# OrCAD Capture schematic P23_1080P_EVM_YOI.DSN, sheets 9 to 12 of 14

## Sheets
9 P08: Frame Buffer Memory: size D
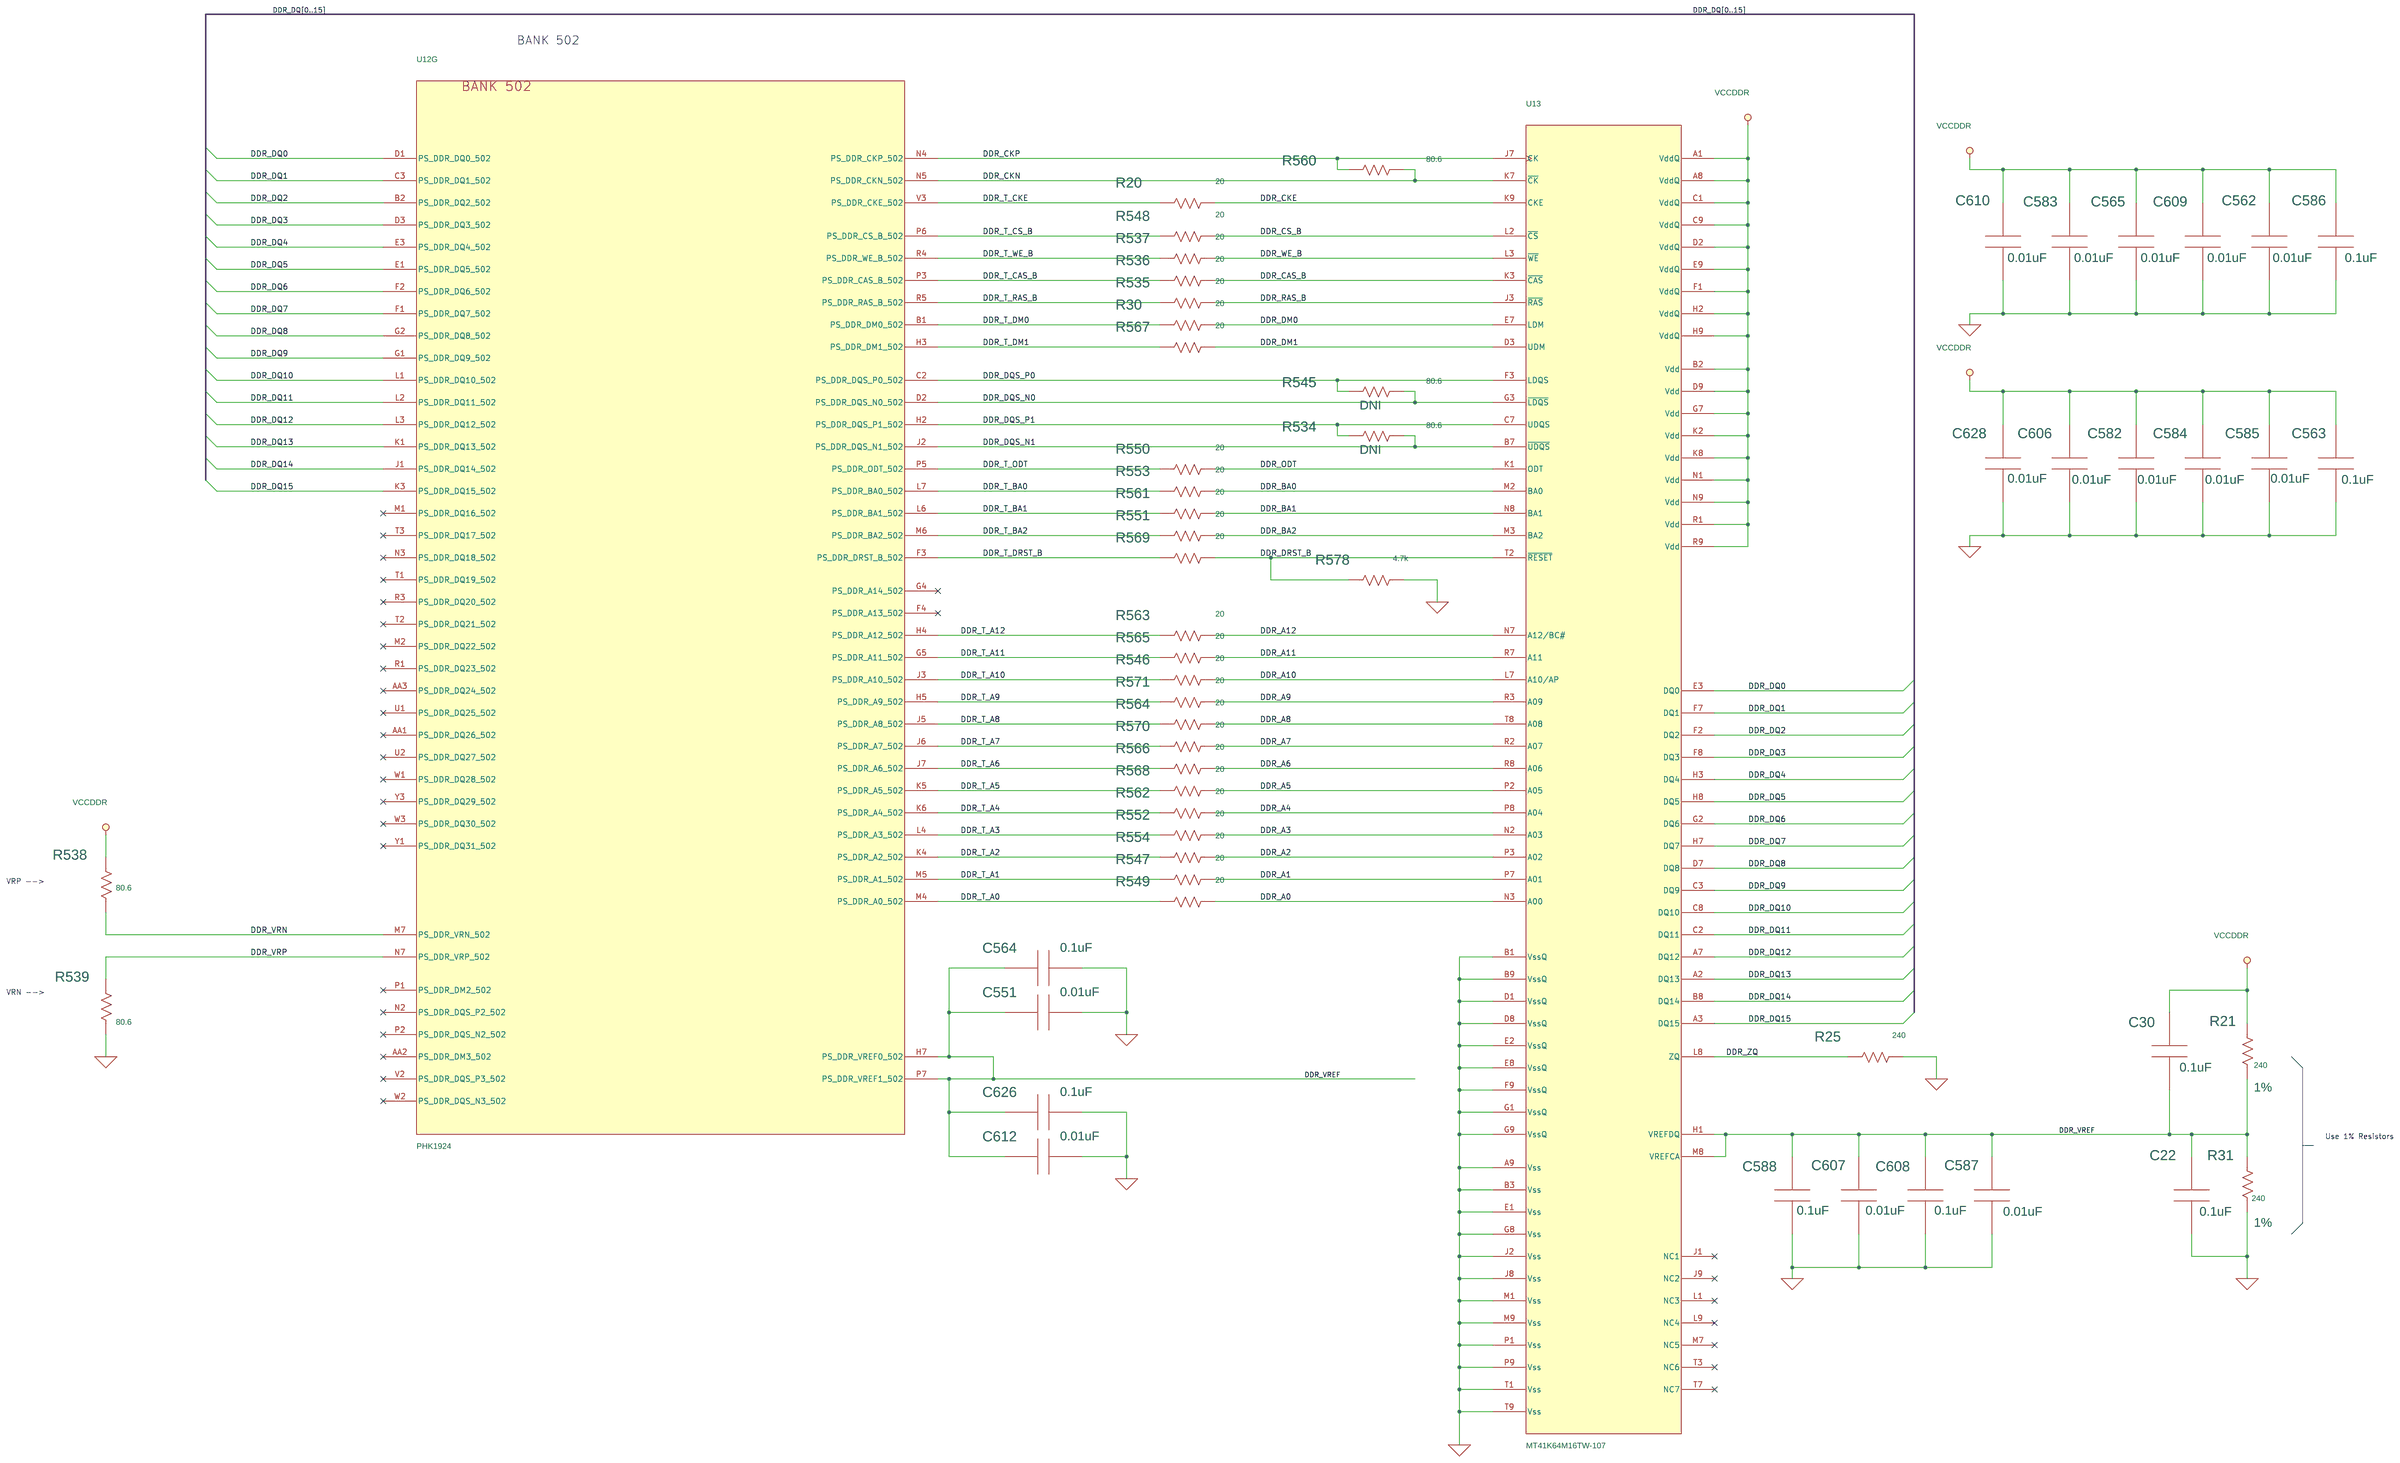
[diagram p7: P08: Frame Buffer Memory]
10 P09: FPGA Parallal Video IN: size D
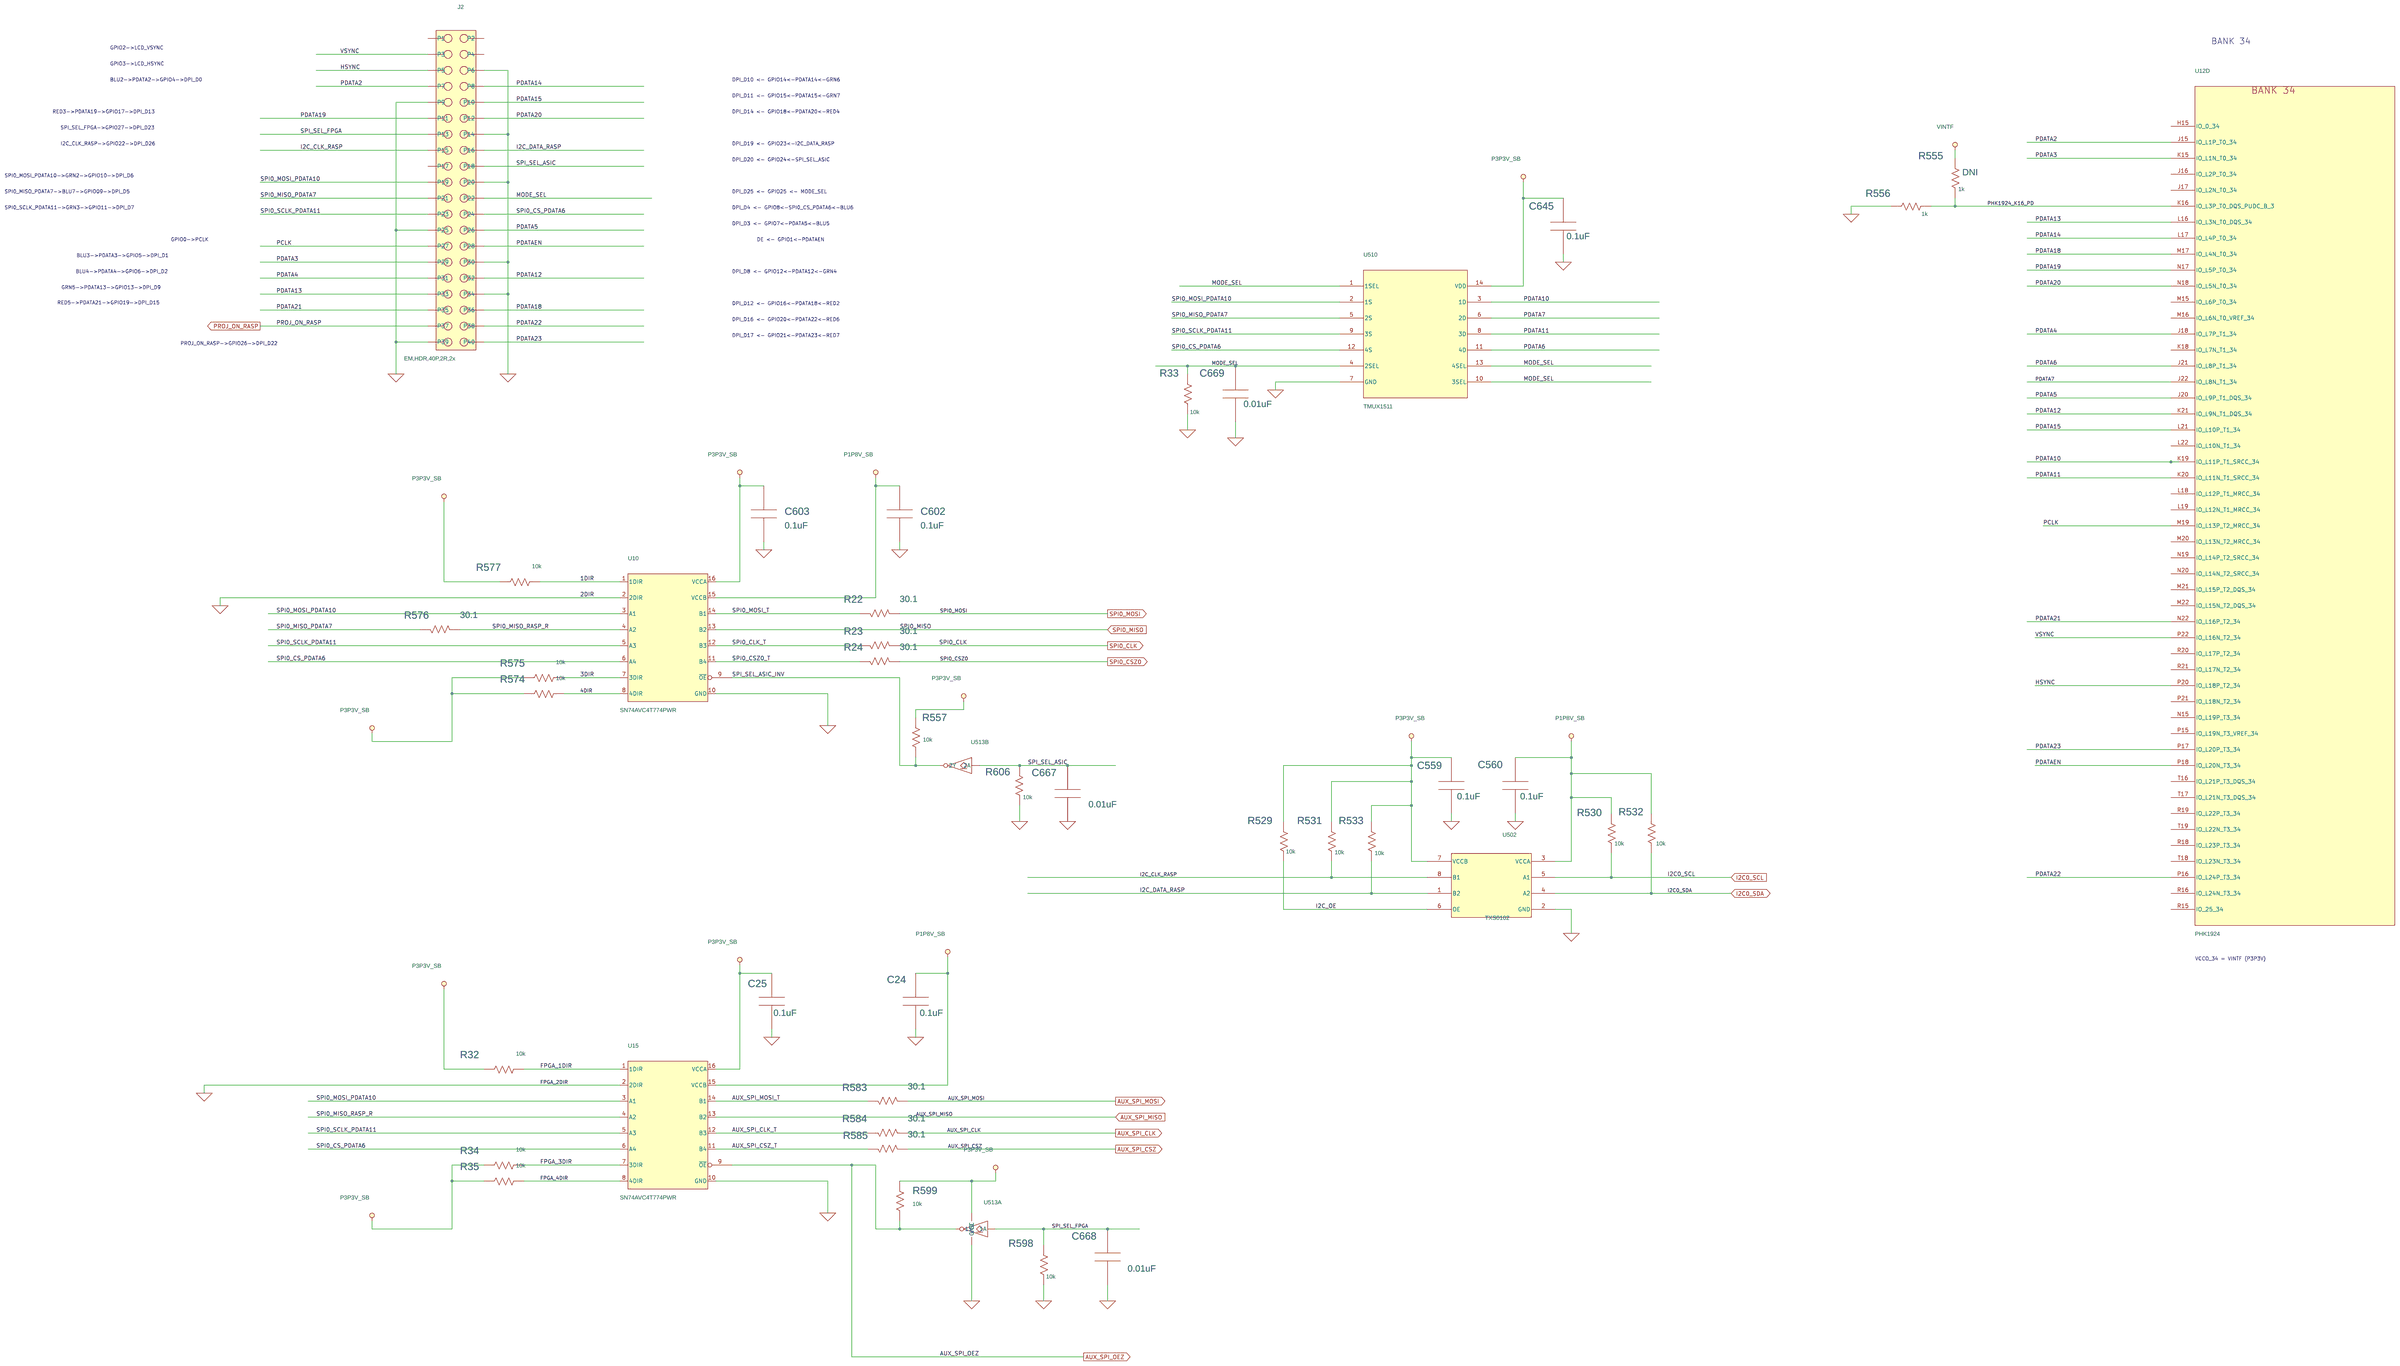
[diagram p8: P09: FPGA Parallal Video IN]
11 P02: BOOT, FLSH, RST,DEBUG: size D
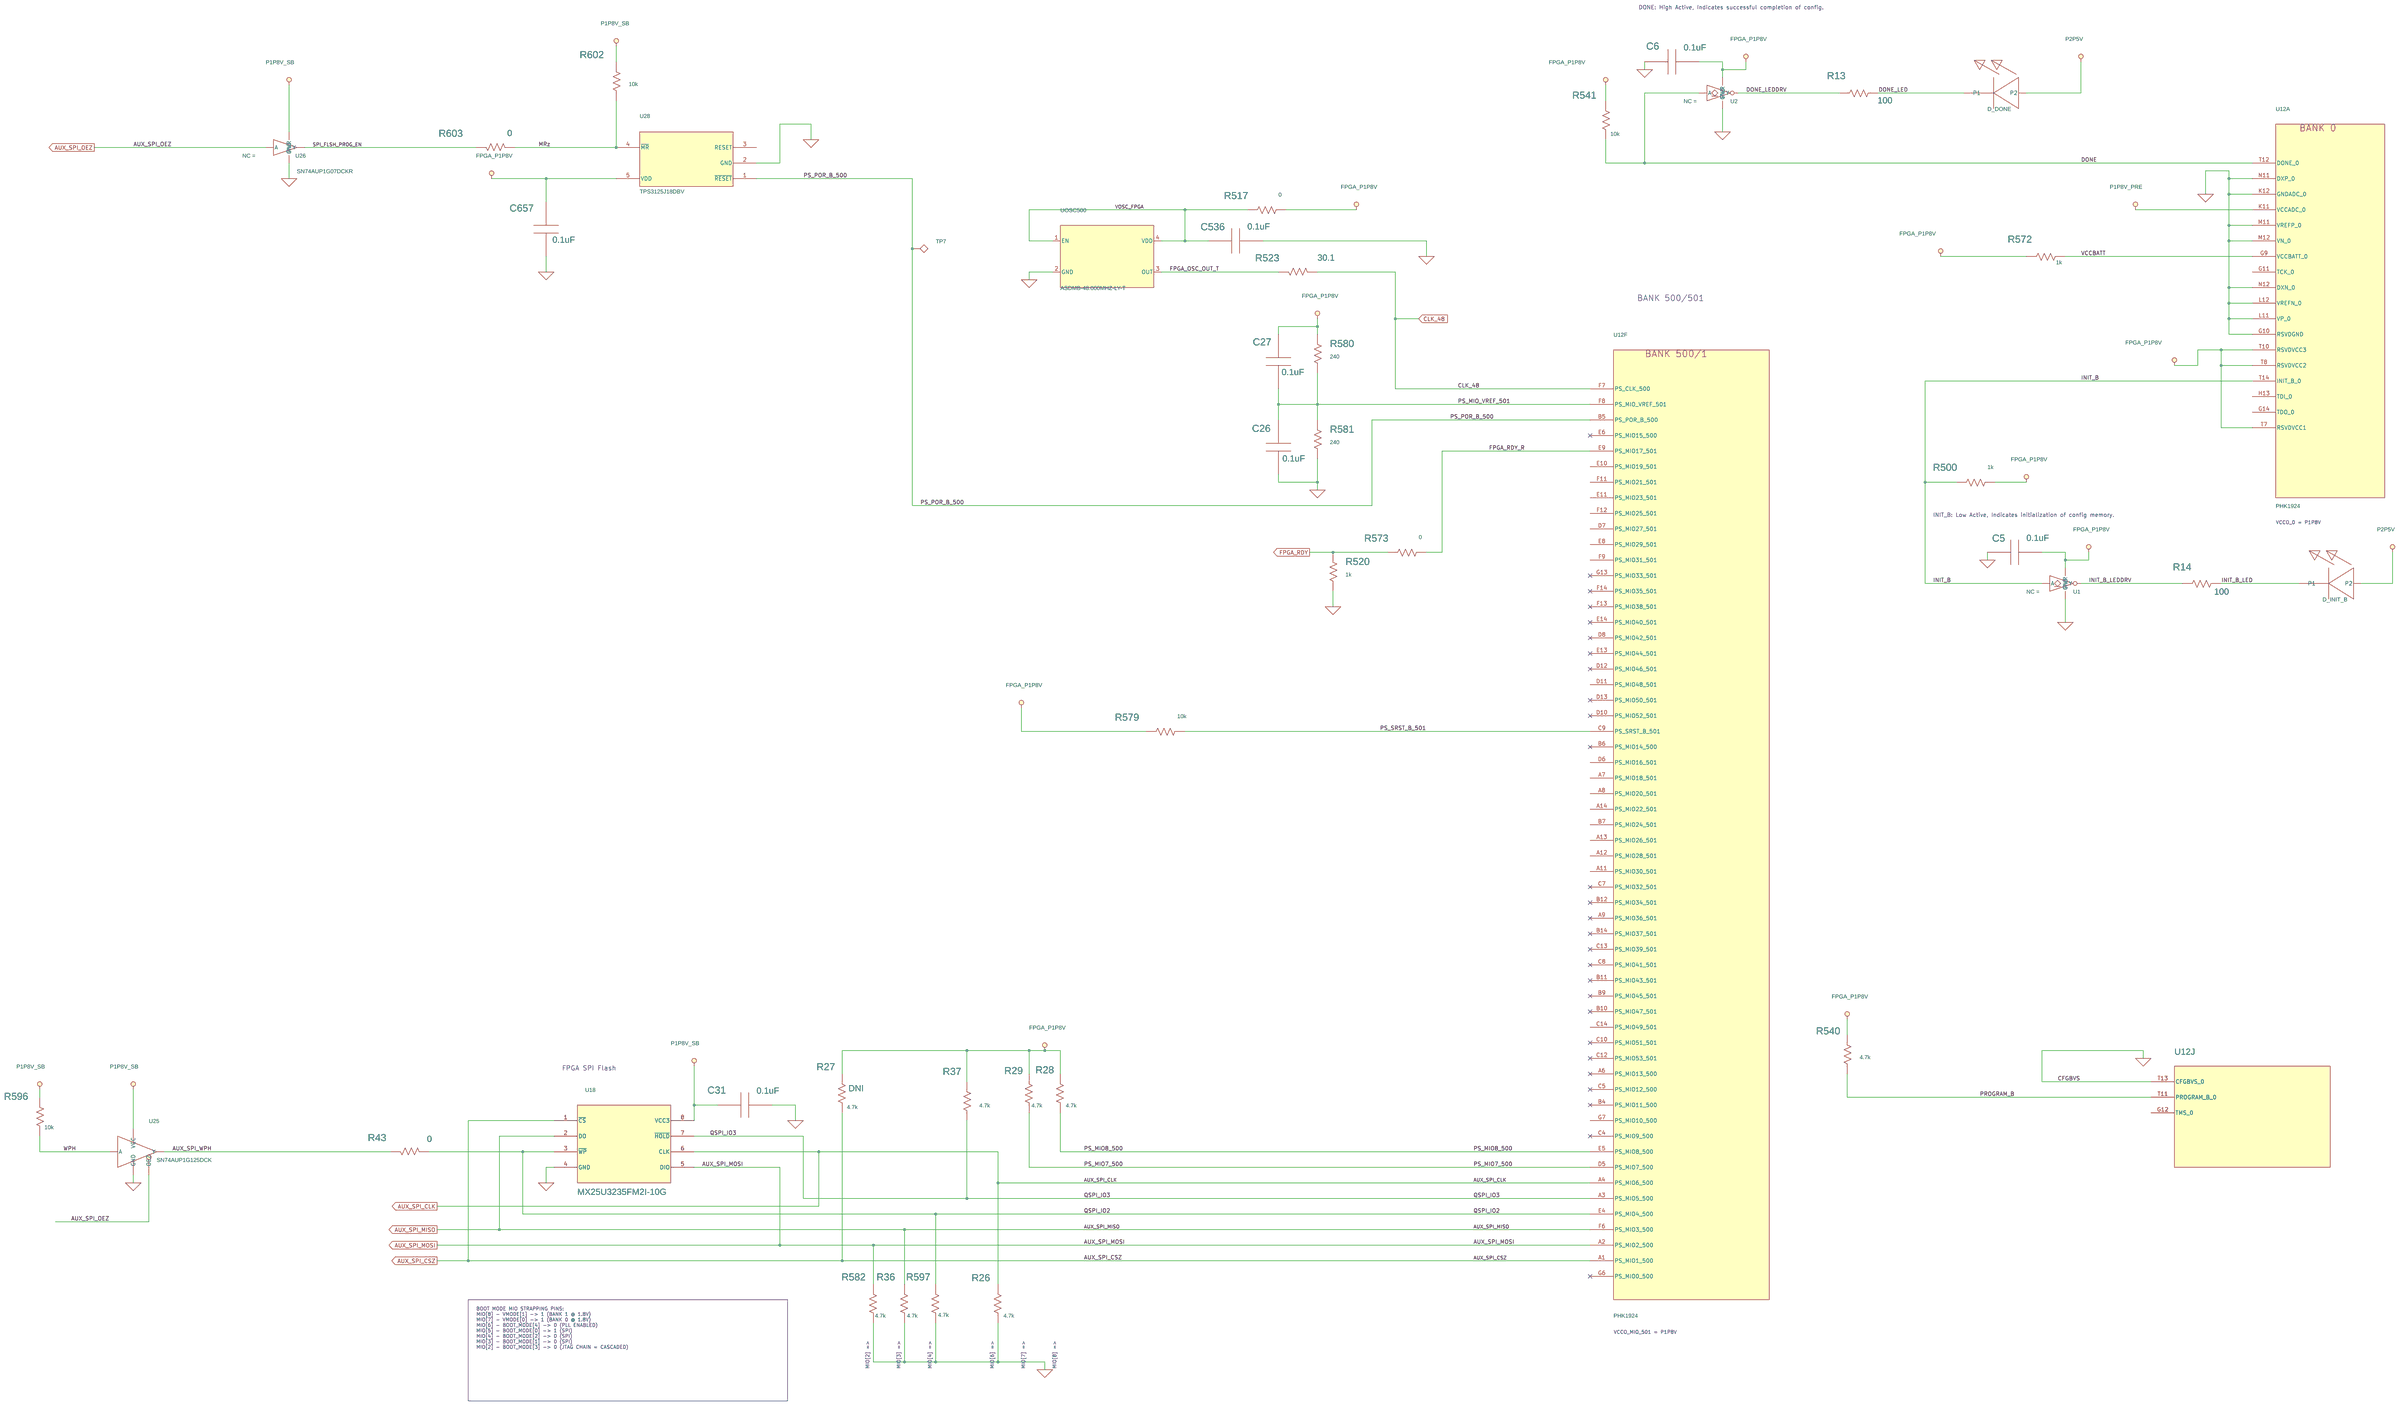
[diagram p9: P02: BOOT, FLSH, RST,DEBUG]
12 P06: DLPC3436 Parallel Video IN: size D
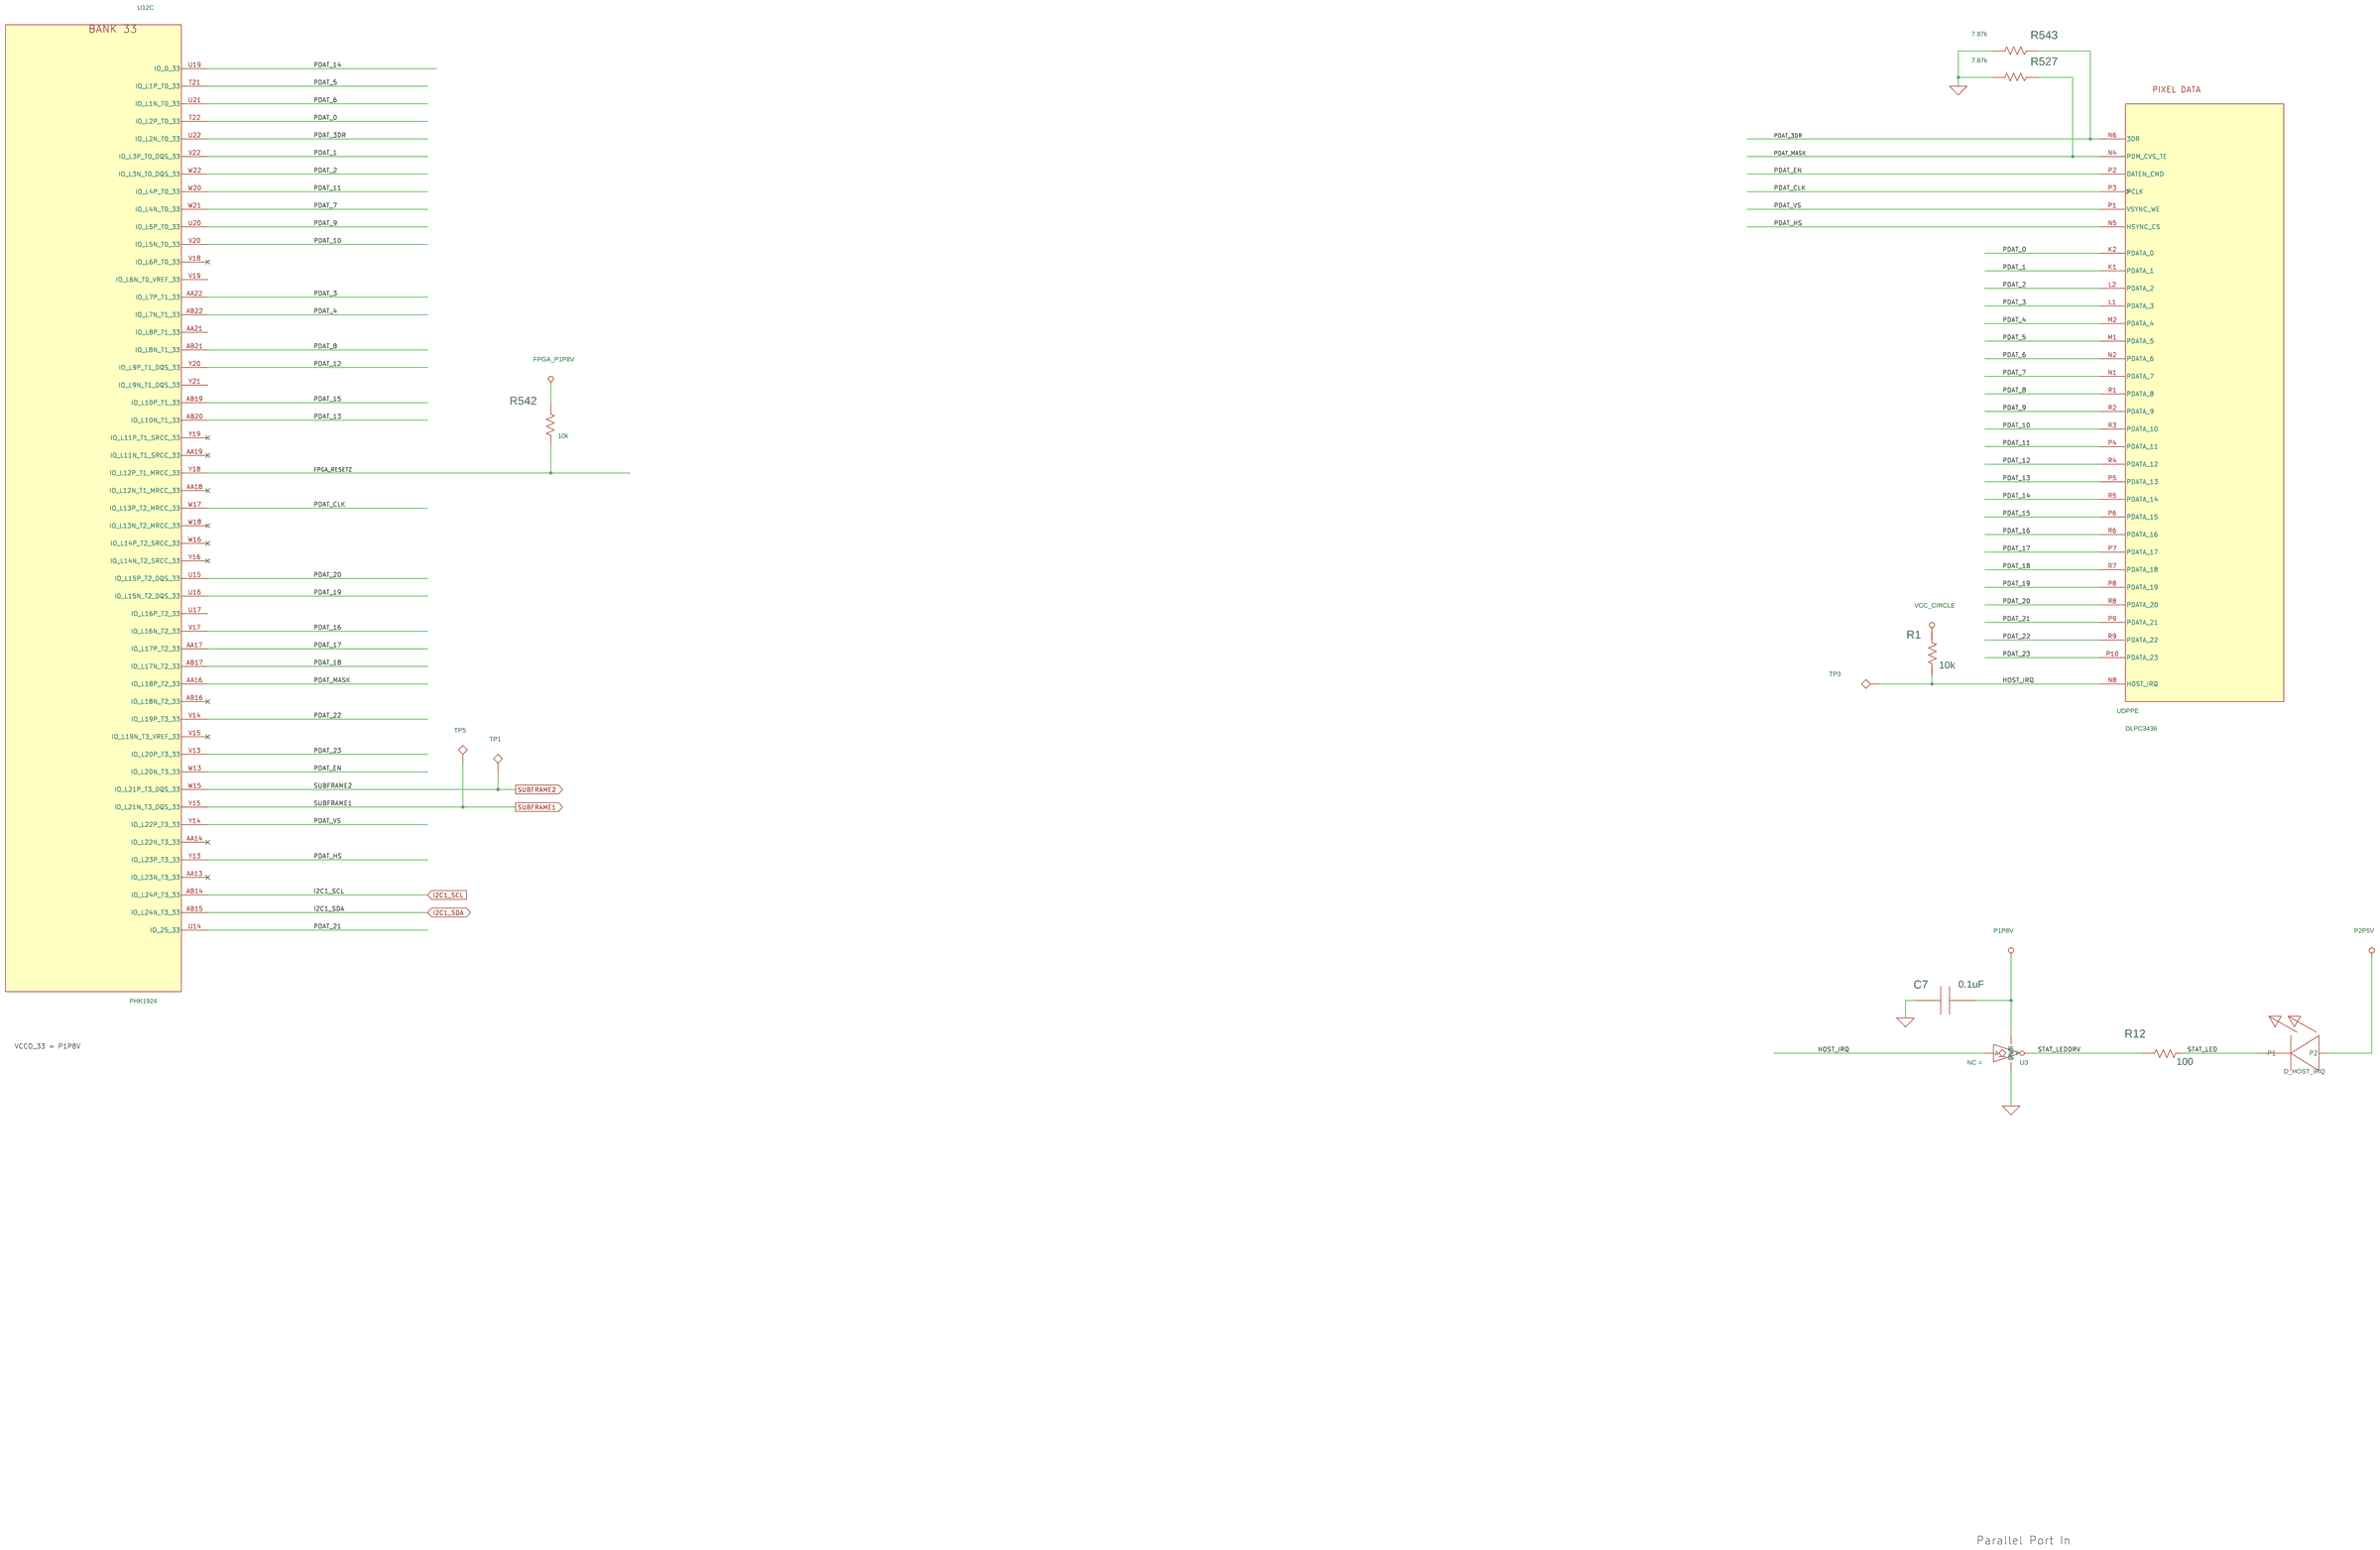
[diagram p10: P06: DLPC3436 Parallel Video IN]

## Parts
sheet P02: BOOT, FLSH, RST,DEBUG
C5  0.1uF  [0402_AVXA]
C6  0.1uF  [0402_AVXA]
C26  0.1uF  [0402_AVXA]
C27  0.1uF  [0402_AVXA]
C31  0.1uF  [0402_AVXA]
C536  0.1uF  [0402_AVXA]
C657  0.1uF  [0402_AVXA]
D_DONE  green  [1206]
D_INIT_B  green  [1206]
R13  100  [0402]
R14  100  [0402]
R26  4.7k  [0402]
R27  4.7k  [0402]
R28  4.7k  [0402]
R29  4.7k  [0402]
R36  4.7k  [0402]
R37  4.7k  [0402]
R43  0  [0402]
R500  1k  [0402]
R517  0  [0402]
R520  1k  [0402]
R523  30.1  [0402]
R540  4.7k  [0402]
R541  10k  [0402]
R572  1k  [0402]
R573  0  [0402]
R579  10k  [0402]
R580  240  [0402]
R581  240  [0402]
R582  4.7k  [0402]
R596  10k  [0402]
R597  4.7k  [0402]
R602  10k  [0402]
R603  0  [0402]
TP7  TP40  [TP40]
U1  SN74AUP1G06DCK  [U_5_DCK]
U2  SN74AUP1G06DCK  [U_5_DCK]
U18  MX25U3235FM2I-10G  [SOIC-8_208mil]
U25  SN74AUP1G125DCK  [U_5_DCK]
U26  SN74AUP1G07DCK  [U_5_DCK]
U28  TPS3125J18DBV  [DBV_R-PDS0-G5]
UOSC500  48MHz  [ECS-2018_2p5mmx2mm]
sheet P06: DLPC3436 Parallel Video IN
C7  0.1uF  [0402_AVXA]
D_HOST_IRQ  green  [1206]
R1  10k  [0402]
R12  100  [0402]
R527  7.87k  [0402]
R542  10k  [0402]
R543  7.87k  [0402]
TP1  TP,20mil PAD  [tp20rd]
TP3  TP40  [TP40]
TP5  TP40  [TP40]
U3  SN74AUP1G06DCK  [U_5_DCK]
sheet P08: Frame Buffer Memory
C22  0.1uF  [0402_AVXA]
C30  0.1uF  [0402_AVXA]
C551  0.01uF  [0402]
C562  0.01uF  [0402]
C563  0.1uF  [0402_AVXA]
C564  0.1uF  [0402_AVXA]
C565  0.01uF  [0402]
C582  0.01uF  [0402]
C583  0.01uF  [0402]
C584  0.01uF  [0402]
C585  0.01uF  [0402]
C586  0.1uF  [0402_AVXA]
C587  0.01uF  [0402]
C588  0.1uF  [0402_AVXA]
C606  0.01uF  [0402]
C607  0.01uF  [0402]
C608  0.1uF  [0402_AVXA]
C609  0.01uF  [0402]
C610  0.01uF  [0402]
C612  0.01uF  [0402]
C626  0.1uF  [0402_AVXA]
C628  0.01uF  [0402]
R20  20  [0201_R]
R21  240  [0402]
R25  240  [0402]
R30  20  [0201_R]
R31  240  [0402]
R534  80.6  [0402]
R535  20  [0201_R]
R536  20  [0201_R]
R537  20  [0201_R]
R538  80.6  [0402]
R539  80.6  [0402]
R545  80.6  [0402]
R546  20  [0201_R]
R547  20  [0201_R]
R548  20  [0201_R]
R549  20  [0201_R]
R550  20  [0201_R]
R551  20  [0201_R]
R552  20  [0201_R]
R553  20  [0201_R]
R554  20  [0201_R]
R560  80.6  [0402]
R561  20  [0201_R]
R562  20  [0201_R]
R563  20  [0201_R]
R564  20  [0201_R]
R565  20  [0201_R]
R566  20  [0201_R]
R567  20  [0201_R]
R568  20  [0201_R]
R569  20  [0201_R]
R570  20  [0201_R]
R571  20  [0201_R]
R578  4.7k  [0402]
U12  PHK1924  [Xilinx_CLG484]  (sections A,B,C,D,E,F,G,H,I,J)
U13  MT41K64M16TW-107  [Micron_96-ball_FBGA-x16_TW]
sheet P09: FPGA Parallal Video IN
C24  0.1uF  [0402_AVXA]
C25  0.1uF  [0402_AVXA]
C559  0.1uF  [0402_AVXA]
C560  0.1uF  [0402_AVXA]
C602  0.1uF  [0402_AVXA]
C603  0.1uF  [0402_AVXA]
C645  0.1uF  [0402_AVXA]
C667  0.01uF  [0402]
C668  0.01uF  [0402]
C669  0.01uF  [0402]
J2  EM,HDR,40P,2R,2x  [MINI_HDR20X2]
R22  30.1  [0402]
R23  30.1  [0402]
R24  30.1  [0402]
R32  10k  [0402]
R33  10k  [0402]
R34  10k  [0402]
R35  10k  [0402]
R529  10k  [0402]
R530  10k  [0402]
R531  10k  [0402]
R532  10k  [0402]
R533  10k  [0402]
R555  1k  [0402]
R556  1k  [0402]
R557  10k  [0402]
R574  10k  [0402]
R575  10k  [0402]
R576  30.1  [0402]
R577  10k  [0402]
R583  30.1  [0402]
R584  30.1  [0402]
R585  30.1  [0402]
R598  10k  [0402]
R599  10k  [0402]
R606  10k  [0402]
U10  SN74AVC4T774PWR  [TSSOP16_PW]
U15  SN74AVC4T774PWR  [TSSOP16_PW]
U502  TXS0102  [VSSOP-8_DCU]
U510  TMUX1511  [TSSOP14_PW]
U513  SN74AUP2G06DCKR  [U_6_DCK]  (sections A,B)
sheet P10: DLPA2005
UDPP  DLPC3436  [DPP3433_7mmx7mm_VFBGA_176balls]  (sections A,B,C,D,E,F,G,H)

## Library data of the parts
C5-C7 C22 C24-C27 C30 C31 C536 C559 C560 C563 C564 C586 C588 C602 C603 C608 C626 C645 = PAS,CAP,NP,large: DigiKey: 490-7998-1-ND; DigiReel: 490-7998-6-ND; Family: passive; Lead Style: SMT; MFG: Murata; Material: x7r; P/D_NUM: GCM155R71C104KA55J; Part Number: GCM155R71C104KA55J; Part Specific: CAP CER .1UF 16V X7R 0402; TOLERANCE: 10%; Type: capacitor; VENDOR: Murata; VPC: 16V
C657 = PAS,CAP,NP,large: DigiKey: 490-7998-1-ND; DigiReel: 490-7998-6-ND; Family: passive; Install: Y; Lead Style: SMT; MFG: Murata; Material: x7r; P/D_NUM: GCM155R71C104KA55J; Part Number: GCM155R71C104KA55J; Part Specific: CAP CER .1UF 16V X7R 0402; TOLERANCE: 10%; Type: capacitor; VENDOR: Murata; VPC: 16V
D_DONE D_HOST_IRQ D_INIT_B = PAS,DIODE,LED,large: DigiKey: 67-1357-1-ND; DigiReel: 67-1357-6-ND; Family: passive; Index PN: 31; Install: Y; Lead Style: SMT; MFG: Lumex; P/D_NUM: SML-LX1206GC-TR; Part Number: SML-LX1206GC-TR; Part Specific: LED 565NM WTR CLR GREEN 1206 SMD; Type: diode,led; VENDOR: Lumex
R12-R14 = PAS,R,large: DigiKey: P100LCT-ND; DigiReel: P100LDKR-ND; Family: passive; Index PN: 690; Lead Style: SMT; MFG: Panasonic; Material: chip; P/D_NUM: ERJ-2RKF1000X; Part Number: ERJ-2RKF1000X; Part Specific: RES 100 OHM 1/10W 1% 0402 SMD; Power: 1/16W; TOLERANCE: 1%; Type: resistor; VENDOR: Panasonic; VPC: 1/16W
R26 R28 R29 R36 R37 R540 R578 R597 = PAS,R,large: DigiKey: P4.70KLCT-ND; DigiReel: P4.70KLDKR-ND; Family: passive; Index PN: 1219; Lead Style: SMT; MFG: Panasonic; P/D_NUM: ERJ-2RKF4701X; Part Number: ERJ-2RKF4701X; Part Specific: RES 4.7K OHM 1/10W 1% 0402 SMD; Type: resistor; VENDOR: Panasonic; VPC: 1/16W
R27 = PAS,R,large: DigiKey: P4.70KLCT-ND; DigiReel: P4.70KLDKR-ND; Family: passive; Index PN: 1219; Install: DNI; Lead Style: SMT; MFG: Panasonic; P/D_NUM: ERJ-2RKF4701X; Part Number: ERJ-2RKF4701X; Part Specific: RES 4.7K OHM 1/10W 1% 0402 SMD; Type: resistor; VENDOR: Panasonic; VPC: 1/16W
R43 R603 = PAS,R,large: DigiKey: P0.0JCT-ND; DigiReel: P0.0JDKR-ND; Family: passive; Index PN: 687; Install: Y; Lead Style: SMT; MFG: Panasonic; Material: chip; P/D_NUM: ERJ-2GE0R00X; Part Number: ERJ-2GE0R00X; Part Specific: RES 0.0 OHM 1/16W 0402 SMD; Power: 1/16W; Type: resistor; VPC: 1/16W; Vendor: Panasonic
R500 R520 R556 R572 = PAS,R,large: DigiKey: P1.00KLCT-ND; DigiReel: P1.00KLDKR-ND; Family: passive; Index PN: 684; Install: Y; Lead Style: SMT; MFG: Panasonic; Material: chip; P/D_NUM: ERJ-2RKF1001X; Part Number: ERJ-2RKF1001X; Part Specific: RES 1.00K OHM 1/10W 1% 0402 SMD; Power: 1/16W; TOLERANCE: 1%; Type: resistor; VENDOR: Panasonic; VPC: 1/16W
R517 R573 = PAS,R,large: DigiKey: P0.0JCT-ND; DigiReel: P0.0JDKR-ND; Family: passive; Index PN: 687; Lead Style: SMT; MFG: Panasonic; Material: chip; P/D_NUM: ERJ-2GE0R00X; Part Number: ERJ-2GE0R00X; Part Specific: RES 0.0 OHM 1/16W 0402 SMD; Power: 1/16W; Type: resistor; VENDOR: Panasonic; VPC: 1/16W
R22-R24 R523 R576 R583-R585 = PAS,R,large: DigiKey: YAG3111CT-ND; DigiReel: P30.1LDKR-ND; Family: passive; Index PN: 976; Lead Style: SMT; MFG: Yageo; Material: chip; P/D_NUM: RC0402FR-0730R1L; Part Number: RC0402FR-0730R1L; Part Specific: RES 30.1 OHM 1/16W 1% 0402 SMD; Power: 1/16W; TOLERANCE: 1%; Type: resistor; VENDOR: Yageo; VPC: 1/16W
R541 R542 R579 R596 R602 = PAS,R,large: DigiKey: P10.0KLCT-ND; DigiReel: P10.0KLDKR-ND; Family: passive; Index PN: 680; Install: Y; Lead Style: SMT; MFG: Panasonic; Material: chip; P/D_NUM: ERJ-2RKF1002X; Part Number: ERJ-2RKF1002X; Part Specific: RES SMD 10K OHM 1% 1/10W 0402; Power: 1/16W; TOLERANCE: 1%; Type: resistor; VENDOR: Panasonic; VPC: 1/16W
R21 R25 R31 R580 R581 = PAS,R,large: DigiKey: P240LCT-ND; DigiReel: P240LDKR-ND; Family: passive; Index PN: 1303; Lead Style: SMT; MFG: Panasonic; P/D_NUM: ERJ-2RKF2400X; Part Number: ERJ-2RKF2400X; Part Specific: RES SMD 240 OHM 1% 1/10W 0402; TOLERANCE: 1%; Type: resistor; VENDOR: Panasonic; VPC: 1/16W
R582 = PAS,R,large: DigiKey: P4.70KLCT-ND; DigiReel: P4.70KLDKR-ND; Family: passive; Index PN: 1219; Install: Y; Lead Style: SMT; MFG: Panasonic; P/D_NUM: ERJ-2RKF4701X; Part Number: ERJ-2RKF4701X; Part Specific: RES 4.7K OHM 1/10W 1% 0402 SMD; Type: resistor; VENDOR: Panasonic; VPC: 1/16W
TP3 TP5 TP7 = EM,TERM,TESTPOINT: DigiKey: ---; DigiReel: ---; Family: board feature; Index PN: 995; Install: DNI; MFG: -- NOT A PART --; Type: hole,plated; Vendor: -- NOT A PART --
U1-U3 = LOG,INV,OPENDRN,SN74AUP1G06DCK: DigiKey: 296-17562-1-ND; DigiReel: 296-17562-6-ND; Family: logic; Index PN: 1026; Lead Style: SMT; MFG: Texas Instruments; P/D_NUM: SN74AUP1G06DCKR; Part Number: SN74AUP1G06DCKR; Part Specific: IC INVERTER SINGLE 1INPUT SC705, open drain; Type: buffer
U18 = MEM,FLASH,SERIAL,W25XxxALxNIG: DigiKey: 1092-1137-ND; DigiReel: ---; Family: memory; Install: Y; Lead Style: SMT; MFG: Macronix; Part Specific: IC FLASH 32MBIT 104MHZ 8SOIC; Type: flash, spi; VENDOR: Macronix; VPC: 1.65-1.95V
U25 = LOG,BUF,SN74AUP1G125DCK: DigiKey: 296-21012-1-ND; DigiReel: 296-21012-6-ND; Family: logic; Lead Style: SMT; MFG: Texas Instruments; P/D_NUM: SN74AUP1G125DCKR; Part Number: SN74AUP1G125DCKR; Part Specific: IC BUS BUFFER TRI-ST SC70-5; Pin Cnt: 5; Type: buffer
U26 = LOG,BUF,OPENDRN,SN74AUP1G07DCK: DigiKey: 296-18256-1-ND; DigiReel: 296-18256-6-ND; Family: logic; Index PN: 1027; Lead Style: SMT; MFG: Texas Instruments; P/D_NUM: SN74AUP1G07DCKR; Part Number: SN74AUP1G07DCKR; Part Specific: IC BUFF/DVR LOW PWR N-INV SC705, open drain; Type: buffer
U28 = PWR,MON,TPS3125: DigiKey: 296-10898-1-ND; DigiReel: 296-10898-6-ND; Family: power; Index PN: 1160; Install: Y; Lead Style: SMT; MFG: Texas Instruments; Part Specific: IC 1.62V SUPPLY MONITOR SOT23-5; Type: monitor; Vendor: Texas Instruments
UOSC500 = ANA,OSC,4P,2X: DigiKey: 535-11198-1-ND; DigiReel: 535-11198-6-ND; Family: analog; Index PN: 1346; Install: Y; Lead Style: SMT; MFG: Abracon; P/D_NUM: ASDMB-48.000MHZ-LY-T; Part Number: ASDMB-48.000MHZ-LY-T; Part Specific: OSC MEMS 48.000MHZ CMOS SMD; Type: oscillator; VPC: 1.8V-3.3V; Vendor: Abracon
R1 R529 = PAS,R,large: DigiKey: P10.0KLCT-ND; DigiReel: P10.0KLDKR-ND; Family: passive; Index PN: 680; Install: Y; Lead Style: SMT; MFG: Panasonic; Material: chip; P/D_NUM: ERJ-2RKF1002X; Part Number: ERJ-2RKF1002X; Part Specific: RES SMD 10K OHM 1% 1/10W 0402; Power: 1/16W; TOLERANCE: 1%; Type: resistor; VPC: 1/16W; Vendor: Panasonic
R527 R543 = PAS,R,large: DigiKey: P7.87KLCT-ND; DigiReel: P7.87KLDKR-ND; Family: passive; Index PN: 1175; Lead Style: SMT; MFG: Panasonic; Material: chip; P/D_NUM: ERJ-2RKF7871X; Part Number: ERJ-2RKF7871X; Part Specific: RES 7.87K OHM 1/10W 1% 0402 SMD; Type: resistor; VENDOR: Panasonic; VPC: 1/10W
TP1 = BF,HOLE,PLATED,TESTPIN: Family: board feature; Index PN: 1145; Install: DNI; Lead Style: SMT; MFG: -- NOT A PART --; Type: pad pattern; Vendor: -- NOT A PART --
C551 C562 C565 C582-C585 C587 C606 C607 C609 C610 C612 C628 = PAS,CAP,NP,large: DigiKey: 399-1038-1-ND; DigiReel: 399-1038-6-ND; Family: passive; Lead Style: SMT; MFG: KEMET; Material: x7r; P/D_NUM: C0402C103K4RACTU; Part Number: C0402C103K4RACTU; Part Specific: CAP CER 10000PF 16V X7R 0402; TOLERANCE: 10%; Type: capacitor; VENDOR: KEMET; VPC: 16V
R20 R30 R535-R537 R546-R554 R561-R571 = PAS,R,large: DigiKey: P20.0ABCT-ND; DigiReel: P20.0ABDKR-ND; Family: passive; Index PN: 1361; Install: Y; Lead Style: SMT; MFG: Panasonic; P/D_NUM: ERJ-1GEF20R0C; Part Number: ERJ-1GEF20R0C; Part Specific: RES SMD 20 OHM 1% 1/20W 0201; Power: 1%; Type: resistor; VENDOR: Panasonic; VPC: 1/20W
R534 R545 = PAS,R,large: DigiKey: P80.6LCT-ND; DigiReel: P80.6LDKR-ND; Family: passive; Index PN: 1385; Install: DNI; Lead Style: SMT; MFG: Panasonic; P/D_NUM: ERJ-2RKF80R6X; Part Number: ERJ-2RKF80R6X; Part Specific: 80.6 Ohm ±1% 0.1W 1/10W Chip Resistor 0402 (1005 Metric) Automotive AEC-Q200 Thick Film; Type: resistor; VENDOR: Panasonic; VPC: 1/16W
R538 R539 = PAS,R,large: DigiKey: P80.6LCT-ND; DigiReel: P80.6LDKR-ND; Family: passive; Index PN: 1385; Lead Style: SMT; MFG: Panasonic; P/D_NUM: ERJ-2RKF80R6X; Part Number: ERJ-2RKF80R6X; Part Specific: 80.6 Ohm ±1% 0.1W 1/10W Chip Resistor 0402 (1005 Metric) Automotive AEC-Q200 Thick Film; Type: resistor; VENDOR: Panasonic; VPC: 1/16W
R560 = PAS,R,large: DigiKey: P80.6LCT-ND; DigiReel: P80.6LDKR-ND; Family: passive; Index PN: 1385; Install: Y; Lead Style: SMT; MFG: Panasonic; P/D_NUM: ERJ-2RKF80R6X; Part Number: ERJ-2RKF80R6X; Part Specific: 80.6 Ohm ±1% 0.1W 1/10W Chip Resistor 0402 (1005 Metric) Automotive AEC-Q200 Thick Film; Type: resistor; VENDOR: Panasonic; VPC: 1/16W
U12 = TIDLP,XPR_FPGA,Zynq-7020new: DigiKey: ---; DigiReel: ---; Family: processor; Index PN: 1304; Lead Style: SMT; MFG: Xilinx; P/D_NUM: XC7Z020-1CLG484I4493; Part Number: XC7Z020-1CLG484I4493; Part Specific: Xilinx FPGA XC7Z020-1CLG484I; Type: dlp; Vendor: Xilinx
U13 = MEM,SDRAM,DDR3,8Mx16x4banks_0: DigiKey: 557-1765-ND; DigiReel: ---; Family: memory; Index PN: 1302; Lead Style: SMT; MFG: Micron; P/D_NUM: MT41K64M16TW-107:J; Part Number: MT41K64M16TW-107:J; Part Specific: IC DDR3 SDRAM 1Gb (64MX16) 96FBGA; Temp: I; Type: sdram,ddr3; Vendor: Micron
C667-C669 = PAS,CAP,NP,large: DigiKey: 399-1038-1-ND; DigiReel: 399-1038-6-ND; Family: passive; Install: Y; Lead Style: SMT; MFG: KEMET; Material: x7r; P/D_NUM: C0402C103K4RACTU; Part Number: C0402C103K4RACTU; Part Specific: CAP CER 10000PF 16V X7R 0402; TOLERANCE: 10%; Type: capacitor; VENDOR: KEMET; VPC: 16V
J2 = EM,HDR,40P,2R,2x: DigiKey: 732-5313-ND; MFG: Wurth Electronics Inc.; P/D_NUM: 61308021121; Part Number: 61308021121; Part Specific: CONN HEADER VERT 80POS 2.54MM; VENDOR: Wurth Electronics Inc.
R32-R35 R530-R533 R557 R574 R575 R577 R598 R599 R606 = PAS,R,large: DigiKey: P10.0KLCT-ND; DigiReel: P10.0KLDKR-ND; Family: passive; Index PN: 680; Lead Style: SMT; MFG: Panasonic; Material: chip; P/D_NUM: ERJ-2RKF1002X; Part Number: ERJ-2RKF1002X; Part Specific: RES SMD 10K OHM 1% 1/10W 0402; Power: 1/16W; TOLERANCE: 1%; Type: resistor; VENDOR: Panasonic; VPC: 1/16W
R555 = PAS,R,large: DigiKey: P1.00KLCT-ND; DigiReel: P1.00KLDKR-ND; Family: passive; Index PN: 684; Install: DNI; Lead Style: SMT; MFG: Panasonic; Material: chip; P/D_NUM: ERJ-2RKF1001X; Part Number: ERJ-2RKF1001X; Part Specific: RES 1.00K OHM 1/10W 1% 0402 SMD; Power: 1/16W; TOLERANCE: 1%; Type: resistor; VENDOR: Panasonic; VPC: 1/16W
U10 U15 = LOG,XCVR,SN74AVC4T774PW,4_0: DigiKey: 296-24739-1-ND; DigiReel: 296-24739-6-ND; Part Specific: IC BUS TRANSCVR 4BIT DL 16TSSOP; Type: transceiver
U502 = TXS0102: DigiKey: 296-21931-1-ND; DigiReel: 296-21931-6-ND; Family: interface; Index PN: 877; Install: Y; Lead Style: SMT; MFG: Texas Instruments; P/D_NUM: TXS0102DCUR; Part Number: TXS0102DCUR; Part Specific: IC VOLT-LEVEL TRANSLATOR 8-US8; Type: driver; VENDOR: Texas Instruments
U510 = LOG,MUX,1511: DigiKey: 296-53442-1-ND; DigiReel: 296-53442-6-ND; P/D_NUM: TMUX1511PWR; Part Number: TMUX1511PWR; Part Specific: IC SWITCH SPST QUAD 14TSSOP; Type: switch; VENDOR: Texas Instruments
U513 = LOG,INV,OPENDRN,SN74AUP2G06DCK.: DigiKey: 296-27354-1-ND; DigiReel: 296-27354-2-ND; Install: Y; Lead Style: SMT; MFG: Texas Instruments; Part Specific: IC INVERTER 2CH 2-INP SC70-6; Type: Inverter; VENDOR: Texas Instruments
UDPP = TIDLP,DPP3430,_no_DSI: DigiKey: ---; DigiReel: ---; Family: processor; Lead Style: SMT; MFG: Texas Instruments; Mouser: ---; P/D_NUM: DLPC3436CZVBR; Part Number: DLPC3436CZVBR; Part Specific: DLP-PICO Processor; Type: dlp; Vendor: Texas Instruments; Install: Y

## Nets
GND: C5.1(P) C6.1(P) C7.1(P) C22.2(N) C24.2(N) C25.2(N) C26.2(N) C31.2(N) C536.2(N) C551.2(N) C559.2(N) C560.2(N) C562.2(N) C563.2(N) C564.2(N) C565.2(N) C582.2(N) C583.2(N) C584.2(N) C585.2(N) C586.2(N) C587.2(N) C588.2(N) C602.2(N) C603.2(N) C606.2(N) C607.2(N) C608.2(N) C609.2(N) C610.2(N) C612.2(N) C626.2(N) C628.2(N) C645.2(N) C657.2(N) C667.1(P) C668.1(P) C669.1(P) J2.6(P6) J2.9(P9) J2.14(P14) J2.20(P20) J2.25(P25) J2.30(P30) J2.34(P34) J2.39(P39) R25.1(N1) R26.1(N1) R31.2(N2) R33.2(N2) R36.1(N1) R520.2(N2) R527.1(N1) R539.2(N2) R543.1(N1) R556.2(N2) R578.1(N1) R581.2(N2) R582.1(N1) R597.1(N1) R598.2(N2) R606.1(N1) U1.3(GND) U2.3(GND) U3.3(GND) U10.2(2DIR) U10.10(GND) U12.G10(RSVDGND) U12.K12(GNDADC_0) U12.L11(VP_0) U12.L12(VREFN_0) U12.M11(VREFP_0) U12.M12(VN_0) U12.N11(DXP_0) U12.N12(DXN_0) U12.T13(CFGBVS_0) U13.A9(Vss) U13.B1(VssQ) U13.B3(Vss) U13.B9(VssQ) U13.D1(VssQ) U13.D8(VssQ) U13.E1(Vss) U13.E2(VssQ) U13.E8(VssQ) U13.F9(VssQ) U13.G1(VssQ) U13.G8(Vss) U13.G9(VssQ) U13.J2(Vss) U13.J8(Vss) U13.M1(Vss) U13.M9(Vss) U13.P1(Vss) U13.P9(Vss) U13.T1(Vss) U13.T9(Vss) U15.2(2DIR) U15.10(GND) U18.4(GND) U25.3(GND) U26.3(GND) U28.2(GND) U502.2(GND) U510.7(GND) U513.2(GND) UOSC500.2(GND) ; also on sheet 1 2 4 6 7 8 13 14
VCCBATT: R572.1(N1) U12.G9(VCCBATT_0)
VCCDDR: C30.1(P) C562.1(P) C563.1(P) C565.1(P) C582.1(P) C583.1(P) C584.1(P) C585.1(P) C586.1(P) C606.1(P) C609.1(P) C610.1(P) C628.1(P) R21.1(N1) R538.1(N1) U13.A1(VddQ) U13.A8(VddQ) U13.B2(Vdd) U13.C1(VddQ) U13.C9(VddQ) U13.D2(VddQ) U13.D9(Vdd) U13.E9(VddQ) U13.F1(VddQ) U13.G7(Vdd) U13.H2(VddQ) U13.H9(VddQ) U13.K2(Vdd) U13.K8(Vdd) U13.N1(Vdd) U13.N9(Vdd) U13.R1(Vdd) U13.R9(Vdd) ; also on sheet 2
VINTF: R555.1(N1) ; also on sheet 2
1DIR: R577.1(N1) U10.1(1DIR)
3DIR: R575.1(N1) U10.7(3DIR)
4DIR: R574.1(N1) U10.8(4DIR)
AUX_SPI_CLK: R26.2(N2) R584.1(N1) U12.A4(PS_MIO6_500) U18.6(CLK)
AUX_SPI_CLK_T: R584.2(N2) U15.12(B3)
AUX_SPI_CSZ: R27.1(N1) R585.1(N1) U12.A1(PS_MIO1_500) U18.1(~{CS})
AUX_SPI_CSZ_T: R585.2(N2) U15.11(B4)
AUX_SPI_MISO: R36.2(N2) U12.F6(PS_MIO3_500) U15.13(B2) U18.2(DO)
AUX_SPI_MOSI: R582.2(N2) R583.1(N1) U12.A2(PS_MIO2_500) U18.5(DIO)
AUX_SPI_MOSI_T: R583.2(N2) U15.14(B1)
AUX_SPI_OEZ: R599.2(N2) U15.9(~{OE}) U25.1(OEZ) U26.2(A) U513.6(1Y)
AUX_SPI_WPH: R43.2(N2) U25.4(Y)
CLK_48: R523.1(N1) U12.F7(PS_CLK_500) ; also on sheet 7
DDR_A0: R549.1(N1) U13.N3(A00)
DDR_A1: R547.1(N1) U13.P7(A01)
DDR_A2: R554.1(N1) U13.P3(A02)
DDR_A3: R552.1(N1) U13.N2(A03)
DDR_A4: R562.1(N1) U13.P8(A04)
DDR_A5: R568.1(N1) U13.P2(A05)
DDR_A6: R566.1(N1) U13.R8(A06)
DDR_A7: R570.1(N1) U13.R2(A07)
DDR_A8: R564.1(N1) U13.T8(A08)
DDR_A9: R571.1(N1) U13.R3(A09)
DDR_A10: R546.1(N1) U13.L7(A10/AP)
DDR_A11: R565.1(N1) U13.R7(A11)
DDR_A12: R563.1(N1) U13.N7(A12/BC#)
DDR_BA0: R553.1(N1) U13.M2(BA0)
DDR_BA1: R561.1(N1) U13.N8(BA1)
DDR_BA2: R551.1(N1) U13.M3(BA2)
DDR_CAS_B: R536.1(N1) U13.K3(~{CAS})
DDR_CKE: R20.1(N1) U13.K9(CKE)
DDR_CKN: R560.1(N1) U12.N5(PS_DDR_CKN_502) U13.K7(~{CK})
DDR_CKP: R560.2(N2) U12.N4(PS_DDR_CKP_502) U13.J7(CK)
DDR_CS_B: R548.1(N1) U13.L2(~{CS})
DDR_DM0: R30.1(N1) U13.E7(LDM)
DDR_DM1: R567.1(N1) U13.D3(UDM)
DDR_DQ0: U12.D1(PS_DDR_DQ0_502) U13.E3(DQ0)
DDR_DQ1: U12.C3(PS_DDR_DQ1_502) U13.F7(DQ1)
DDR_DQ2: U12.B2(PS_DDR_DQ2_502) U13.F2(DQ2)
DDR_DQ3: U12.D3(PS_DDR_DQ3_502) U13.F8(DQ3)
DDR_DQ4: U12.E3(PS_DDR_DQ4_502) U13.H3(DQ4)
DDR_DQ5: U12.E1(PS_DDR_DQ5_502) U13.H8(DQ5)
DDR_DQ6: U12.F2(PS_DDR_DQ6_502) U13.G2(DQ6)
DDR_DQ7: U12.F1(PS_DDR_DQ7_502) U13.H7(DQ7)
DDR_DQ8: U12.G2(PS_DDR_DQ8_502) U13.D7(DQ8)
DDR_DQ9: U12.G1(PS_DDR_DQ9_502) U13.C3(DQ9)
DDR_DQ10: U12.L1(PS_DDR_DQ10_502) U13.C8(DQ10)
DDR_DQ11: U12.L2(PS_DDR_DQ11_502) U13.C2(DQ11)
DDR_DQ12: U12.L3(PS_DDR_DQ12_502) U13.A7(DQ12)
DDR_DQ13: U12.K1(PS_DDR_DQ13_502) U13.A2(DQ13)
DDR_DQ14: U12.J1(PS_DDR_DQ14_502) U13.B8(DQ14)
DDR_DQ15: U12.K3(PS_DDR_DQ15_502) U13.A3(DQ15)
DDR_DQS_N0: R545.1(N1) U12.D2(PS_DDR_DQS_N0_502) U13.G3(~{LDQS})
DDR_DQS_N1: R534.1(N1) U12.J2(PS_DDR_DQS_N1_502) U13.B7(~{UDQS})
DDR_DQS_P0: R545.2(N2) U12.C2(PS_DDR_DQS_P0_502) U13.F3(LDQS)
DDR_DQS_P1: R534.2(N2) U12.H2(PS_DDR_DQS_P1_502) U13.C7(UDQS)
DDR_DRST_B: R569.1(N1) R578.2(N2) U13.T2(~{RESET})
DDR_ODT: R550.1(N1) U13.K1(ODT)
DDR_RAS_B: R535.1(N1) U13.J3(~{RAS})
DDR_T_A0: R549.2(N2) U12.M4(PS_DDR_A0_502)
DDR_T_A1: R547.2(N2) U12.M5(PS_DDR_A1_502)
DDR_T_A2: R554.2(N2) U12.K4(PS_DDR_A2_502)
DDR_T_A3: R552.2(N2) U12.L4(PS_DDR_A3_502)
DDR_T_A4: R562.2(N2) U12.K6(PS_DDR_A4_502)
DDR_T_A5: R568.2(N2) U12.K5(PS_DDR_A5_502)
DDR_T_A6: R566.2(N2) U12.J7(PS_DDR_A6_502)
DDR_T_A7: R570.2(N2) U12.J6(PS_DDR_A7_502)
DDR_T_A8: R564.2(N2) U12.J5(PS_DDR_A8_502)
DDR_T_A9: R571.2(N2) U12.H5(PS_DDR_A9_502)
DDR_T_A10: R546.2(N2) U12.J3(PS_DDR_A10_502)
DDR_T_A11: R565.2(N2) U12.G5(PS_DDR_A11_502)
DDR_T_A12: R563.2(N2) U12.H4(PS_DDR_A12_502)
DDR_T_BA0: R553.2(N2) U12.L7(PS_DDR_BA0_502)
DDR_T_BA1: R561.2(N2) U12.L6(PS_DDR_BA1_502)
DDR_T_BA2: R551.2(N2) U12.M6(PS_DDR_BA2_502)
DDR_T_CAS_B: R536.2(N2) U12.P3(PS_DDR_CAS_B_502)
DDR_T_CKE: R20.2(N2) U12.V3(PS_DDR_CKE_502)
DDR_T_CS_B: R548.2(N2) U12.P6(PS_DDR_CS_B_502)
DDR_T_DM0: R30.2(N2) U12.B1(PS_DDR_DM0_502)
DDR_T_DM1: R567.2(N2) U12.H3(PS_DDR_DM1_502)
DDR_T_DRST_B: R569.2(N2) U12.F3(PS_DDR_DRST_B_502)
DDR_T_ODT: R550.2(N2) U12.P5(PS_DDR_ODT_502)
DDR_T_RAS_B: R535.2(N2) U12.R5(PS_DDR_RAS_B_502)
DDR_T_WE_B: R537.2(N2) U12.R4(PS_DDR_WE_B_502)
DDR_VREF: C22.1(P) C30.2(N) C551.1(P) C564.1(P) C587.1(P) C588.1(P) C607.1(P) C608.1(P) C612.1(P) C626.1(P) R21.2(N2) R31.1(N1) U12.H7(PS_DDR_VREF0_502) U12.P7(PS_DDR_VREF1_502) U13.H1(VREFDQ) U13.M8(VREFCA)
DDR_VRN: R538.2(N2) U12.M7(PS_DDR_VRN_502)
DDR_VRP: R539.1(N1) U12.N7(PS_DDR_VRP_502)
DDR_WE_B: R537.1(N1) U13.L3(~{WE})
DDR_ZQ: R25.2(N2) U13.L8(ZQ)
DONE: R541.2(N2) U2.2(A) U12.T12(DONE_0)
DONE_LED: D_DONE.1(P1) R13.1(N1)
DONE_LEDDRV: R13.2(N2) U2.4(Y)
FPGA_1DIR: R32.1(N1) U15.1(1DIR)
FPGA_3DIR: R34.1(N1) U15.7(3DIR)
FPGA_4DIR: R35.1(N1) U15.8(4DIR)
FPGA_OSC_OUT_T: R523.2(N2) UOSC500.3(OUT)
FPGA_P1P8V: C5.2(N) C6.2(N) C27.2(N) C657.1(P) R27.2(N2) R28.2(N2) R29.2(N2) R37.1(N1) R500.1(N1) R517.1(N1) R540.1(N1) R541.1(N1) R542.2(N2) R572.2(N2) R579.2(N2) R580.1(N1) U1.5(PWR) U2.5(PWR) U12.T7(RSVDVCC1) U12.T8(RSVDVCC2) U12.T10(RSVDVCC3) U28.5(VDD) ; also on sheet 2 7
FPGA_RDY: R520.1(N1) R573.2(N2) ; also on sheet 1 7
FPGA_RDY_R: R573.1(N1) U12.E9(PS_MIO17_501)
FPGA_RESETZ: R542.1(N1) U12.Y18(IO_L12P_T1_MRCC_33)
HOST_IRQ: R1.2(N2) TP3.1(P1) U3.2(A) UDPP.N8(HOST_IRQ)
HSYNC: J2.5(P5) U12.P20(IO_L18P_T2_34)
I2C0_SCL: R530.2(N2) U502.5(A1) ; also on sheet 4
I2C0_SDA: R532.2(N2) U502.4(A2) ; also on sheet 4
I2C1_SCL: U12.AB14(IO_L24P_T3_33) ; also on sheet 4
I2C1_SDA: U12.AB15(IO_L24N_T3_33) ; also on sheet 4
I2C_CLK_RASP: J2.15(P15) R531.2(N2) U502.8(B1)
I2C_DATA_RASP: J2.16(P16) R533.2(N2) U502.1(B2)
I2C_OE: R529.2(N2) U502.6(OE)
INIT_B: R500.2(N2) U1.2(A) U12.T14(INIT_B_0)
INIT_B_LED: D_INIT_B.1(P1) R14.1(N1)
INIT_B_LEDDRV: R14.2(N2) U1.4(Y)
MODE_SEL: C669.2(N) J2.22(P22) R33.1(N1) U510.1(1SEL) U510.4(2SEL) U510.10(3SEL) U510.13(4SEL)
MRz: R602.2(N2) R603.1(N1) U28.4(~{MR})
P1P8V: C7.2(N) R1.1(N1) U3.5(PWR) ; also on sheet 1 4 6 14
P1P8V_PRE: U12.K11(VCCADC_0) ; also on sheet 2
P1P8V_SB: C24.1(P) C31.1(P) C560.1(P) C602.1(P) R530.1(N1) R532.1(N1) R596.1(N1) R602.1(N1) U10.15(VCCB) U15.15(VCCB) U18.8(VCC3) U25.5(VCC) U26.5(PWR) U502.3(VCCA) ; also on sheet 1 2 4 6 7 13
P2P5V: D_DONE.2(P2) D_HOST_IRQ.2(P2) D_INIT_B.2(P2) ; also on sheet 2
P3P3V_SB: C25.1(P) C559.1(P) C603.1(P) C645.1(P) R32.2(N2) R34.2(N2) R35.2(N2) R529.1(N1) R531.1(N1) R533.1(N1) R557.1(N1) R574.2(N2) R575.2(N2) R577.2(N2) R599.1(N1) U10.16(VCCA) U15.16(VCCA) U502.7(VCCB) U510.14(VDD) U513.5(VCC) ; also on sheet 2 7 13
PCLK: J2.27(P27) U12.M19(IO_L13P_T2_MRCC_34)
PDAT_0: U12.T22(IO_L2P_T0_33) UDPP.K2(PDATA_0)
PDAT_1: U12.V22(IO_L3P_T0_DQS_33) UDPP.K1(PDATA_1)
PDAT_2: U12.W22(IO_L3N_T0_DQS_33) UDPP.L2(PDATA_2)
PDAT_3: U12.AA22(IO_L7P_T1_33) UDPP.L1(PDATA_3)
PDAT_3DR: R543.2(N2) U12.U22(IO_L2N_T0_33) UDPP.N6(3DR)
PDAT_4: U12.AB22(IO_L7N_T1_33) UDPP.M2(PDATA_4)
PDAT_5: U12.T21(IO_L1P_T0_33) UDPP.M1(PDATA_5)
PDAT_6: U12.U21(IO_L1N_T0_33) UDPP.N2(PDATA_6)
PDAT_7: U12.W21(IO_L4N_T0_33) UDPP.N1(PDATA_7)
PDAT_8: U12.AB21(IO_L8N_T1_33) UDPP.R1(PDATA_8)
PDAT_9: U12.U20(IO_L5P_T0_33) UDPP.R2(PDATA_9)
PDAT_10: U12.V20(IO_L5N_T0_33) UDPP.R3(PDATA_10)
PDAT_11: U12.W20(IO_L4P_T0_33) UDPP.P4(PDATA_11)
PDAT_12: U12.Y20(IO_L9P_T1_DQS_33) UDPP.R4(PDATA_12)
PDAT_13: U12.AB20(IO_L10N_T1_33) UDPP.P5(PDATA_13)
PDAT_14: U12.U19(IO_0_33) UDPP.R5(PDATA_14)
PDAT_15: U12.AB19(IO_L10P_T1_33) UDPP.P6(PDATA_15)
PDAT_16: U12.V17(IO_L16N_T2_33) UDPP.R6(PDATA_16)
PDAT_17: U12.AA17(IO_L17P_T2_33) UDPP.P7(PDATA_17)
PDAT_18: U12.AB17(IO_L17N_T2_33) UDPP.R7(PDATA_18)
PDAT_19: U12.U16(IO_L15N_T2_DQS_33) UDPP.P8(PDATA_19)
PDAT_20: U12.U15(IO_L15P_T2_DQS_33) UDPP.R8(PDATA_20)
PDAT_21: U12.U14(IO_25_33) UDPP.P9(PDATA_21)
PDAT_22: U12.V14(IO_L19P_T3_33) UDPP.R9(PDATA_22)
PDAT_23: U12.V13(IO_L20P_T3_33) UDPP.P10(PDATA_23)
PDAT_CLK: U12.W17(IO_L13P_T2_MRCC_33) UDPP.P3(PCLK)
PDAT_EN: U12.W13(IO_L20N_T3_33) UDPP.P2(DATEN_CMD)
PDAT_HS: U12.Y13(IO_L23P_T3_33) UDPP.N5(HSYNC_CS)
PDAT_MASK: R527.2(N2) U12.AA16(IO_L18P_T2_33) UDPP.N4(PDM_CVS_TE)
PDAT_VS: U12.Y14(IO_L22P_T3_33) UDPP.P1(VSYNC_WE)
PDATA2: J2.7(P7) U12.J15(IO_L1P_T0_34)
PDATA3: J2.29(P29) U12.K15(IO_L1N_T0_34)
PDATA4: J2.31(P31) U12.J18(IO_L7P_T1_34)
PDATA5: J2.26(P26) U12.J20(IO_L9P_T1_DQS_34)
PDATA6: U12.J21(IO_L8P_T1_34) U510.11(4D)
PDATA7: U12.J22(IO_L8N_T1_34) U510.6(2D)
PDATA10: U12.K19(IO_L11P_T1_SRCC_34) U510.3(1D)
PDATA11: U12.K20(IO_L11N_T1_SRCC_34) U510.8(3D)
PDATA12: J2.32(P32) U12.K21(IO_L9N_T1_DQS_34)
PDATA13: J2.33(P33) U12.L16(IO_L3N_T0_DQS_34)
PDATA14: J2.8(P8) U12.L17(IO_L4P_T0_34)
PDATA15: J2.10(P10) U12.L21(IO_L10P_T1_34)
PDATA18: J2.36(P36) U12.M17(IO_L4N_T0_34)
PDATA19: J2.11(P11) U12.N17(IO_L5P_T0_34)
PDATA20: J2.12(P12) U12.N18(IO_L5N_T0_34)
PDATA21: J2.35(P35) U12.N22(IO_L16P_T2_34)
PDATA22: J2.38(P38) U12.P16(IO_L24P_T3_34)
PDATA23: J2.40(P40) U12.P17(IO_L20P_T3_34)
PDATAEN: J2.28(P28) U12.P18(IO_L20N_T3_34)
PHK1924_K16_PD: R555.2(N2) R556.1(N1) U12.K16(IO_L3P_T0_DQS_PUDC_B_3)
PROGRAM_B: R540.2(N2) U12.T11(PROGRAM_B_0)
PROJ_ON_RASP: J2.37(P37) ; also on sheet 13
PS_MIO7_500: R29.1(N1) U12.D5(PS_MIO7_500)
PS_MIO8_500: R28.1(N1) U12.E5(PS_MIO8_500)
PS_MIO_VREF_501: C26.1(P) C27.1(P) R580.2(N2) R581.1(N1) U12.F8(PS_MIO_VREF_501)
PS_POR_B_500: TP7.1(P1) U12.B5(PS_POR_B_500) U28.1(~{RESET})
PS_SRST_B_501: R579.1(N1) U12.C9(PS_SRST_B_501)
QSPI_IO2: R43.1(N1) R597.2(N2) U12.E4(PS_MIO4_500) U18.3(~{WP})
QSPI_IO3: R37.2(N2) U12.A3(PS_MIO5_500) U18.7(~{HOLD})
SPI0_CLK: R23.1(N1) ; also on sheet 4
SPI0_CLK_T: R23.2(N2) U10.12(B3)
SPI0_CS_PDATA6: J2.24(P24) U10.6(A4) U15.6(A4) U510.12(4S)
SPI0_CSZ0: R24.1(N1) ; also on sheet 4
SPI0_CSZ0_T: R24.2(N2) U10.11(B4)
SPI0_MISO: U10.13(B2) ; also on sheet 4
SPI0_MISO_PDATA7: J2.21(P21) R576.2(N2) U510.5(2S)
SPI0_MISO_RASP_R: R576.1(N1) U10.4(A2) U15.4(A2)
SPI0_MOSI: R22.1(N1) ; also on sheet 4
SPI0_MOSI_PDATA10: J2.19(P19) U10.3(A1) U15.3(A1) U510.2(1S)
SPI0_MOSI_T: R22.2(N2) U10.14(B1)
SPI0_SCLK_PDATA11: J2.23(P23) U10.5(A3) U15.5(A3) U510.9(3S)
SPI_FLSH_PROG_EN: R603.2(N2) U26.4(Y)
SPI_SEL_ASIC: C667.2(N) J2.18(P18) R606.2(N2) U513.3(2A)
SPI_SEL_ASIC_INV: R557.2(N2) U10.9(~{OE}) U513.4(2Y)
SPI_SEL_FPGA: C668.2(N) J2.13(P13) R598.1(N1) U513.1(1A)
STAT_LED: D_HOST_IRQ.1(P1) R12.1(N1)
STAT_LEDDRV: R12.2(N2) U3.4(Y)
SUBFRAME1: TP5.1(P1) U12.Y15(IO_L21N_T3_DQS_33) ; also on sheet 1
SUBFRAME2: TP1.1(P1) U12.W15(IO_L21P_T3_DQS_33) ; also on sheet 1
VOSC_FPGA: C536.1(P) R517.2(N2) UOSC500.1(EN) UOSC500.4(VDD)
VSYNC: J2.3(P3) U12.P22(IO_L16N_T2_34)
WPH: R596.2(N2) U25.2(A)

Not connected (* = marked no-connect by the designer): J2 1(P1) 2(P2) 4(P4) 17(P17); U12 A6(PS_MIO13_500)* A7(PS_MIO18_501) A8(PS_MIO20_501) A9(PS_MIO36_501)* A11(PS_MIO30_501) A12(PS_MIO28_501) A13(PS_MIO26_501) A14(PS_MIO22_501) AA1(PS_DDR_DQ26_502)* AA2(PS_DDR_DM3_502)* AA3(PS_DDR_DQ24_502)* AA13(IO_L23N_T3_33)* AA14(IO_L22N_T3_33)* AA18(IO_L12N_T1_MRCC_33)* AA19(IO_L11N_T1_SRCC_33)* AA21(IO_L8P_T1_33) AB16(IO_L18N_T2_33)* B4(PS_MIO11_500)* B6(PS_MIO14_500)* B7(PS_MIO24_501) B9(PS_MIO45_501)* B10(PS_MIO47_501)* B11(PS_MIO43_501)* B12(PS_MIO34_501)* B14(PS_MIO37_501)* C4(PS_MIO9_500)* C5(PS_MIO12_500)* C7(PS_MIO32_501)* C8(PS_MIO41_501)* C10(PS_MIO51_501)* C12(PS_MIO53_501)* C13(PS_MIO39_501)* C14(PS_MIO49_501) D6(PS_MIO16_501) D7(PS_MIO27_501) D8(PS_MIO42_501)* D10(PS_MIO52_501)* D11(PS_MIO48_501) D12(PS_MIO46_501)* D13(PS_MIO50_501)* E6(PS_MIO15_500)* E8(PS_MIO29_501) E10(PS_MIO19_501) E11(PS_MIO23_501) E13(PS_MIO44_501)* E14(PS_MIO40_501)* F4(PS_DDR_A13_502)* F9(PS_MIO31_501) F11(PS_MIO21_501) F12(PS_MIO25_501) F13(PS_MIO38_501)* F14(PS_MIO35_501)* G4(PS_DDR_A14_502)* G6(PS_MIO0_500)* G7(PS_MIO10_500) G11(TCK_0) G12(TMS_0) G13(PS_MIO33_501)* G14(TDO_0) H13(TDI_0) H15(IO_0_34) J16(IO_L2P_T0_34) J17(IO_L2N_T0_34) K18(IO_L7N_T1_34) L18(IO_L12P_T1_MRCC_34) L19(IO_L12N_T1_MRCC_34) L22(IO_L10N_T1_34) M1(PS_DDR_DQ16_502)* M2(PS_DDR_DQ22_502)* M15(IO_L6P_T0_34) M16(IO_L6N_T0_VREF_34) M20(IO_L13N_T2_MRCC_34) M21(IO_L15P_T2_DQS_34) M22(IO_L15N_T2_DQS_34) N2(PS_DDR_DQS_P2_502)* N3(PS_DDR_DQ18_502)* N15(IO_L19P_T3_34) N19(IO_L14P_T2_SRCC_34) N20(IO_L14N_T2_SRCC_34) P1(PS_DDR_DM2_502)* P2(PS_DDR_DQS_N2_502)* P15(IO_L19N_T3_VREF_34) P21(IO_L18N_T2_34) R1(PS_DDR_DQ23_502)* R3(PS_DDR_DQ20_502)* R15(IO_25_34) R16(IO_L24N_T3_34) R18(IO_L23P_T3_34) R19(IO_L22P_T3_34) R20(IO_L17P_T2_34) R21(IO_L17N_T2_34) T1(PS_DDR_DQ19_502)* T2(PS_DDR_DQ21_502)* T3(PS_DDR_DQ17_502)* T16(IO_L21P_T3_DQS_34) T17(IO_L21N_T3_DQS_34) T18(IO_L23N_T3_34) T19(IO_L22N_T3_34) U1(PS_DDR_DQ25_502)* U2(PS_DDR_DQ27_502)* U17(IO_L16P_T2_33) V2(PS_DDR_DQS_P3_502)* V15(IO_L19N_T3_VREF_33)* V18(IO_L6P_T0_33)* V19(IO_L6N_T0_VREF_33) W1(PS_DDR_DQ28_502)* W2(PS_DDR_DQS_N3_502)* W3(PS_DDR_DQ30_502)* W16(IO_L14P_T2_SRCC_33)* W18(IO_L13N_T2_MRCC_33)* Y1(PS_DDR_DQ31_502)* Y3(PS_DDR_DQ29_502)* Y16(IO_L14N_T2_SRCC_33)* Y19(IO_L11P_T1_SRCC_33)* Y21(IO_L9N_T1_DQS_33); U13 J1(NC1)* J9(NC2)* L1(NC3)* L9(NC4)* M7(NC5)* T3(NC6)* T7(NC7)*; U28 3(RESET)

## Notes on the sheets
sheet 9
- BANK 502
- VRP -->
- VRN -->
- Use 1% Resistors
sheet 10
- BANK 34
- GPIO2->LCD_VSYNC
- GPIO3->LCD_HSYNC
- BLU2->PDATA2->GPIO4->DPI_D0
- DPI_D10 <- GPIO14<-PDATA14<-GRN6
- DPI_D11 <- GPIO15<-PDATA15<-GRN7
- RED3->PDATA19->GPIO17->DPI_D13
- DPI_D14 <- GPIO18<-PDATA20<-RED4
- SPI_SEL_FPGA->GPIO27->DPI_D23
- I2C_CLK_RASP->GPIO22->DPI_D26
- DPI_D19 <- GPIO23<-I2C_DATA_RASP
- DPI_D20 <- GPIO24<-SPI_SEL_ASIC
- SPI0_MOSI_PDATA10->GRN2->GPIO10->DPI_D6
- SPI0_MISO_PDATA7->BLU7->GPIO09->DPI_D5
- DPI_D25 <- GPIO25 <- MODE_SEL
- SPI0_SCLK_PDATA11->GRN3->GPIO11->DPI_D7
- DPI_D4 <- GPIO8<-SPI0_CS_PDATA6<-BLU6
- DPI_D3 <- GPIO7<-PDATA5<-BLU5
- GPIO0->PCLK
- DE <- GPIO1<-PDATAEN
- BLU3->PDATA3->GPIO5->DPI_D1
- BLU4->PDATA4->GPIO6->DPI_D2
- DPI_D8 <- GPIO12<-PDATA12<-GRN4
- GRN5->PDATA13->GPIO13->DPI_D9
- RED5->PDATA21->GPIO19->DPI_D15
- DPI_D12 <- GPIO16<-PDATA18<-RED2
- DPI_D16 <- GPIO20<-PDATA22<-RED6
- PROJ_ON_RASP->GPIO26->DPI_D22
- DPI_D17 <- GPIO21<-PDATA23<-RED7
- VCCO_34 = VINTF (P3P3V)
sheet 11
- DONE: High Active, Indicates successful completion of config.
- BANK 500/501
- INIT_B: Low Active, Indicates initialization of config memory.
- VCCO_0 = P1P8V
- FPGA SPI Flash
- BOOT MODE MIO STRAPPING PINS:
  MIO[8] - VMODE[1] -> 1 (BANK 1 @ 1.8V)
  MIO[7] - VMODE[0] -> 1 (BANK 0 @ 1.8V)
  MIO[6] - BOOT_MODE[4] -> 0 (PLL ENABLED)
  MIO[5] - BOOT_MODE[0] -> 1 (SPI)
  MIO[4] - BOOT_MODE[2] -> 0 (SPI)
  MIO[3] - BOOT_MODE[1] -> 0 (SPI)
  MIO[2] - BOOT_MODE[3] -> 0 (JTAG CHAIN = CASCADED)
- VCCO_MIO_501 = P1P8V
- MIO[2] =>
- MIO[3] =>
- MIO[4] =>
- MIO[6] =>
- MIO[7] =>
- MIO[8] =>
sheet 12
- VCCO_33 = P1P8V
- Parallel Port In
